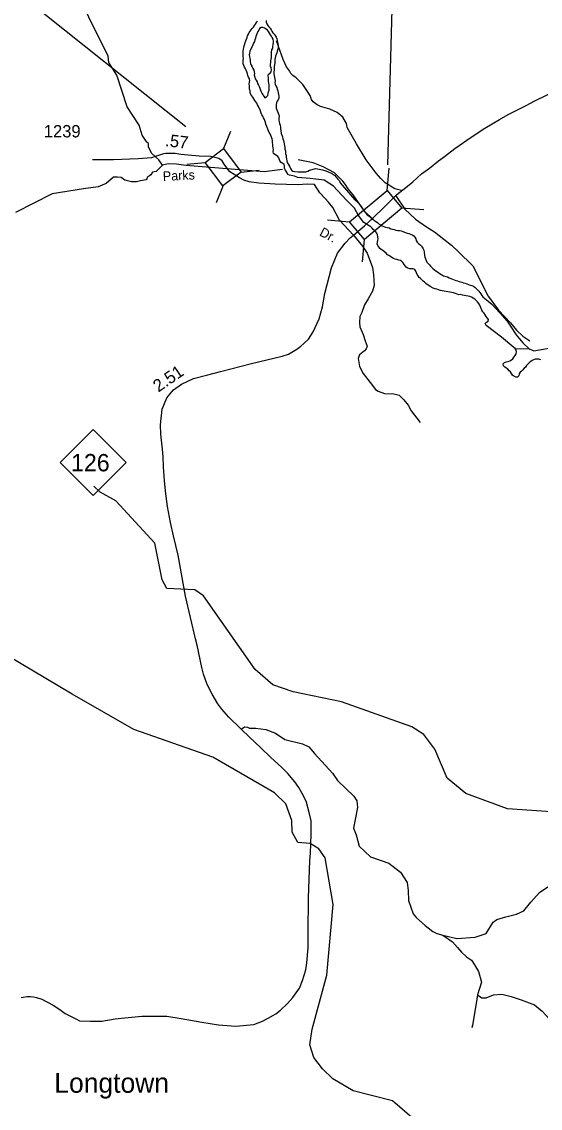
# Model space of a CAD drawing. Extents: x 1113032 to 1302912, y 664689 to 832535.
# Drawn here: x 1139525 to 1144769, y 747949 to 758928 of the extents above; entities that cross this region are included whole.
import ezdxf

# ---------------------------------------------------------------- set-up
doc = ezdxf.new("R2010")
doc.units = 0
for name, color, linetype in [('Exist Civil Demographics Community Label', 7, 'Continuous'), ('Exist Hydrographic Creek Single Shore', 7, 'Continuous'), ('Exist Hydrographic Island Shore', 7, 'Continuous'), ('Exist Hydrographic Lake Shore', 7, 'Continuous'), ('Exist Hydrographic River Shore', 7, 'Continuous'), ('Exist Road Non-System Type 51', 7, 'Continuous'), ('Exist Road Primary NC Attributed', 7, 'Continuous'), ('Exist Road Primary NC Service Mileage Hundredths English Label', 7, 'Continuous'), ('Exist Road Primary NC Shield CELL', 7, 'Continuous'), ('Exist Road Primary NC Shield Number Label', 7, 'Continuous'), ('Exist Road Primary NC Structure Standard Bridge CELL', 7, 'Continuous'), ('Exist Road Primary NC Structure Standard Bridge Number Label', 7, 'Continuous'), ('Exist Road Secondary Mileage Hundredths English Label', 7, 'Continuous'), ('Exist Road Secondary Structure Standard Bridge CELL', 7, 'Continuous'), ('Exist Road Secondary Structure Standard Bridge Number Label', 7, 'Continuous'), ('Exist Road Secondary Type 41 Attributed', 7, 'Continuous'), ('Exist Road Secondary Type 51 Label', 7, 'Continuous'), ('Exist Road Secondary Type 51 Number Label', 7, 'Continuous')]:
    doc.layers.add(name, color=color, linetype=linetype)

msp = doc.modelspace()

# ---------------------------------------------------------------- linework, layer by layer
at = {"layer": 'Exist Hydrographic Creek Single Shore'}
msp.add_line((1141976, 757410), (1141185, 757475), dxfattribs=at)
for points in [[(1140950, 757478), (1140911, 757533), (1140840, 757598), (1140808, 757662), (1140809, 757673), (1140809, 757696), (1140791, 757711), (1140745, 757780), (1140713, 757882), (1140593, 758068), (1140486, 758389), (1140406, 758515), (1140400, 758581), (1140007, 759370), (1139857, 759973), (1139719, 760111), (1139424, 760278)], [(1141185, 757475), (1141092, 757488), (1141006, 757491), (1140950, 757478), (1140886, 757415), (1140848, 757408), (1140830, 757381), (1140817, 757372), (1140795, 757358), (1140792, 757342), (1140785, 757332), (1140728, 757319), (1140687, 757309), (1140634, 757311), (1140568, 757327), (1140531, 757354), (1140493, 757356), (1140455, 757356), (1140380, 757293), (1140300, 757260), (1140150, 757240), (1139834, 757190), (1139461, 757001)], [(1144878, 750945), (1144436, 750974), (1144016, 751130), (1143828, 751284), (1143704, 751579), (1143591, 751726), (1143469, 751804), (1142759, 752057), (1142270, 752156), (1142063, 752229), (1141885, 752383), (1141364, 753126), (1141275, 753187), (1140992, 753202), (1140944, 753289), (1140872, 753658), (1140476, 754086), (1140320, 754174), (1140255, 754235)], [(1143517, 747815), (1143273, 748023), (1142876, 748126), (1142671, 748248), (1142566, 748346), (1142478, 748462), (1142439, 748591), (1142461, 748748), (1142610, 749293), (1142673, 750008), (1142595, 750479), (1142531, 750572), (1142441, 750626), (1142317, 750635), (1142261, 750738), (1142256, 750856), (1142195, 751025), (1142081, 751136), (1141458, 751496), (1140658, 751778), (1140034, 752132), (1139108, 752682)]]:
    msp.add_lwpolyline(points, dxfattribs=at)
at = {"layer": 'Exist Hydrographic Island Shore'}
msp.add_lwpolyline([(1141877, 758387), (1141882, 758369), (1141887, 758352), (1141895, 758336), (1141905, 758321), (1141910, 758303), (1141919, 758288), (1141927, 758272), (1141934, 758255), (1141939, 758238), (1141946, 758221), (1141955, 758205), (1141964, 758190), (1141974, 758175), (1141985, 758160), (1142002, 758170), (1142014, 758183), (1142019, 758202), (1142020, 758220), (1142027, 758237), (1142028, 758254), (1142029, 758272), (1142028, 758290), (1142024, 758308), (1142022, 758326), (1142022, 758344), (1142022, 758362), (1142018, 758380), (1142021, 758397), (1142037, 758408), (1142047, 758423), (1142050, 758443), (1142047, 758461), (1142041, 758478), (1142041, 758497), (1142043, 758515), (1142046, 758533), (1142049, 758551), (1142052, 758568), (1142052, 758586), (1142051, 758604), (1142051, 758622), (1142056, 758644), (1142064, 758661), (1142066, 758679), (1142069, 758697), (1142071, 758715), (1142071, 758733), (1142067, 758750), (1142059, 758767), (1142050, 758782), (1142040, 758797), (1142031, 758813), (1142021, 758828), (1142010, 758842), (1141996, 758853), (1141980, 758862), (1141964, 758868), (1141946, 758870), (1141931, 758859), (1141922, 758844), (1141914, 758828), (1141906, 758812), (1141898, 758795), (1141893, 758778), (1141889, 758761), (1141882, 758744), (1141878, 758727), (1141869, 758711), (1141862, 758694), (1141854, 758678), (1141847, 758662), (1141839, 758645), (1141833, 758629), (1141829, 758611), (1141825, 758593), (1141828, 758576), (1141831, 758558), (1141834, 758540), (1141837, 758522), (1141840, 758505), (1141846, 758488), (1141854, 758472), (1141863, 758456), (1141871, 758440), (1141876, 758423), (1141878, 758405), (1141877, 758387)], dxfattribs=at)
at = {"layer": 'Exist Hydrographic Lake Shore'}
msp.add_line((1144514, 755625), (1144655, 755623), dxfattribs=at)
for points in [[(1144591, 755684), (1144655, 755623), (1144705, 755601), (1144916, 755641), (1145275, 755897), (1145186, 755987), (1145139, 756067), (1145165, 756062), (1145181, 756050), (1145197, 756038)], [(1144774, 755513), (1144755, 755517), (1144736, 755518), (1144717, 755518), (1144687, 755505), (1144672, 755494), (1144657, 755482), (1144642, 755469), (1144630, 755454), (1144618, 755439), (1144605, 755426), (1144592, 755411), (1144578, 755398), (1144564, 755386), (1144554, 755369), (1144552, 755350), (1144540, 755336), (1144521, 755338), (1144503, 755346), (1144489, 755358), (1144477, 755373), (1144467, 755389), (1144454, 755402), (1144441, 755417), (1144427, 755429), (1144410, 755439), (1144396, 755452), (1144394, 755471), (1144406, 755485), (1144424, 755490), (1144443, 755495), (1144461, 755501), (1144478, 755510), (1144492, 755523), (1144503, 755539), (1144514, 755555), (1144525, 755572), (1144529, 755591), (1144525, 755609), (1144514, 755625), (1144502, 755635)]]:
    msp.add_lwpolyline(points, dxfattribs=at)
at = {"layer": 'Exist Hydrographic River Shore'}
for points in [[(1142284, 757367), (1142267, 757372), (1142249, 757374), (1142232, 757376), (1142216, 757385), (1142208, 757401), (1142200, 757417), (1142189, 757432), (1142184, 757449), (1142183, 757467), (1142178, 757484), (1142164, 757495), (1142148, 757505), (1142136, 757521), (1142126, 757551), (1142115, 757566), (1142100, 757575), (1142084, 757585), (1142071, 757597), (1142068, 757616), (1142070, 757634), (1142068, 757653), (1142066, 757671), (1142065, 757689), (1142062, 757707), (1142060, 757724), (1142057, 757743), (1142050, 757760), (1142044, 757777), (1142038, 757794), (1142029, 757809), (1142021, 757826), (1142014, 757843), (1142006, 757860), (1141999, 757876), (1141994, 757894), (1141989, 757911), (1141980, 757940), (1141971, 757956), (1141962, 757972), (1141954, 757988), (1141946, 758004), (1141941, 758023), (1141936, 758040), (1141926, 758055), (1141918, 758071), (1141911, 758088), (1141903, 758104), (1141892, 758119), (1141882, 758133), (1141872, 758149), (1141862, 758164), (1141851, 758178), (1141842, 758193), (1141837, 758210), (1141834, 758228), (1141830, 758245), (1141829, 758263), (1141827, 758281), (1141826, 758299), (1141830, 758317), (1141831, 758334), (1141827, 758352), (1141820, 758369), (1141813, 758386), (1141808, 758403), (1141802, 758420), (1141795, 758437), (1141788, 758453), (1141778, 758470), (1141772, 758487), (1141766, 758504), (1141764, 758522), (1141765, 758540), (1141767, 758558), (1141765, 758576), (1141764, 758594), (1141764, 758612), (1141765, 758630), (1141768, 758649), (1141772, 758667), (1141776, 758684), (1141780, 758702), (1141784, 758719), (1141791, 758736), (1141798, 758752), (1141805, 758769), (1141810, 758786), (1141817, 758803), (1141826, 758818), (1141845, 758846), (1141857, 758859), (1141868, 758874), (1141878, 758889), (1141889, 758902), (1141899, 758919), (1141908, 758934)], [(1141996, 758940), (1141997, 758922), (1142004, 758905), (1142014, 758890), (1142025, 758876), (1142037, 758862), (1142047, 758847), (1142055, 758831), (1142066, 758817), (1142078, 758803), (1142088, 758789), (1142097, 758773), (1142104, 758756)], [(1142104, 758756), (1142110, 758740), (1142113, 758722), (1142115, 758704), (1142117, 758686), (1142118, 758668), (1142116, 758650), (1142110, 758631), (1142105, 758614), (1142099, 758597), (1142091, 758580), (1142087, 758563), (1142085, 758545), (1142086, 758527), (1142084, 758509), (1142080, 758492), (1142079, 758474), (1142078, 758456), (1142077, 758438), (1142075, 758420), (1142074, 758402), (1142078, 758384), (1142081, 758367), (1142085, 758349), (1142087, 758331), (1142086, 758313), (1142089, 758295), (1142096, 758279), (1142104, 758262), (1142109, 758245), (1142115, 758228), (1142120, 758211), (1142123, 758193), (1142124, 758175), (1142124, 758157), (1142120, 758140), (1142110, 758125), (1142101, 758109), (1142097, 758091), (1142097, 758073), (1142099, 758055), (1142106, 758039), (1142113, 758022), (1142120, 758005), (1142126, 757988), (1142127, 757971), (1142125, 757953), (1142125, 757935), (1142128, 757917), (1142133, 757900), (1142138, 757882), (1142142, 757863), (1142143, 757845), (1142145, 757828), (1142148, 757797), (1142155, 757780), (1142163, 757765), (1142167, 757746), (1142171, 757729), (1142175, 757711), (1142178, 757693), (1142182, 757674), (1142185, 757657), (1142186, 757639), (1142193, 757622), (1142194, 757594), (1142198, 757576), (1142200, 757558), (1142203, 757541), (1142206, 757523), (1142211, 757506), (1142226, 757478), (1142235, 757462), (1142244, 757444), (1142254, 757429), (1142268, 757419), (1142286, 757414), (1142322, 757412), (1142344, 757410), (1142375, 757411), (1142398, 757412), (1142419, 757419), (1142435, 757428), (1142500, 757444), (1142551, 757435), (1142568, 757431), (1142599, 757422), (1142625, 757411), (1142649, 757401), (1142668, 757391), (1142687, 757376), (1142704, 757358), (1142723, 757337), (1142738, 757319), (1142747, 757300), (1142830, 757202), (1142890, 757131), (1142927, 757098), (1142947, 757076), (1142959, 757061)], [(1142162, 757434), (1141976, 757410)], [(1144245, 755920), (1144233, 755935), (1144222, 755951), (1144212, 755967), (1144201, 755983), (1144189, 755996), (1144178, 756012), (1144171, 756030), (1144164, 756048), (1144156, 756065), (1144146, 756082), (1144134, 756097), (1144121, 756110), (1144106, 756123), (1144091, 756134), (1144075, 756146), (1144057, 756151), (1144038, 756155), (1144020, 756159), (1144001, 756162), (1143982, 756165), (1143965, 756171), (1143946, 756170), (1143928, 756175), (1143910, 756183), (1143892, 756188), (1143873, 756191), (1143854, 756195), (1143835, 756199), (1143816, 756202), (1143797, 756204), (1143778, 756208), (1143759, 756212), (1143741, 756218), (1143723, 756224), (1143705, 756230), (1143687, 756237), (1143657, 756252), (1143641, 756262), (1143626, 756272), (1143612, 756283), (1143599, 756296), (1143586, 756308), (1143572, 756320), (1143559, 756333), (1143545, 756344), (1143534, 756359), (1143525, 756375), (1143517, 756391), (1143509, 756407), (1143500, 756423), (1143484, 756431), (1143466, 756431), (1143448, 756431), (1143429, 756438), (1143414, 756448), (1143401, 756461), (1143391, 756476), (1143382, 756492), (1143369, 756505), (1143354, 756515), (1143337, 756520), (1143319, 756524), (1143302, 756530), (1143284, 756535), (1143269, 756544), (1143254, 756555), (1143239, 756565), (1143223, 756574), (1143212, 756588), (1143198, 756600), (1143176, 756615), (1143161, 756625), (1143147, 756637), (1143137, 756652), (1143126, 756666), (1143121, 756683), (1143123, 756701), (1143126, 756719), (1143128, 756737), (1143126, 756756), (1143123, 756773), (1143117, 756791), (1143107, 756806), (1143093, 756817), (1143080, 756830), (1143068, 756843), (1143054, 756855), (1143038, 756864), (1142985, 756899), (1142931, 756971), (1142890, 757043), (1142805, 757128), (1142679, 757267), (1142585, 757326), (1142500, 757337), (1142442, 757345), (1142318, 757353), (1142301, 757360), (1142284, 757367)], [(1142959, 757061), (1142969, 757045), (1142977, 757029), (1142991, 757009), (1143004, 756994), (1143019, 756978), (1143035, 756967), (1143050, 756957), (1143096, 756917), (1143112, 756907), (1143126, 756896), (1143139, 756884), (1143155, 756875), (1143171, 756866), (1143188, 756859), (1143205, 756853), (1143223, 756849), (1143240, 756844), (1143257, 756836), (1143274, 756832), (1143292, 756827), (1143309, 756821), (1143327, 756819), (1143345, 756817), (1143363, 756815), (1143380, 756807), (1143406, 756797), (1143423, 756793), (1143441, 756788), (1143458, 756783), (1143475, 756776), (1143489, 756764), (1143500, 756750), (1143509, 756734), (1143515, 756717), (1143524, 756702), (1143537, 756688), (1143550, 756676), (1143563, 756664), (1143575, 756650), (1143585, 756634), (1143593, 756618), (1143596, 756600), (1143597, 756567), (1143601, 756550), (1143608, 756533), (1143616, 756516), (1143623, 756499), (1143636, 756486), (1143648, 756473), (1143659, 756459), (1143672, 756445), (1143684, 756433), (1143699, 756422), (1143714, 756411), (1143728, 756400), (1143743, 756390), (1143758, 756379), (1143773, 756369), (1143790, 756362), (1143813, 756354), (1143830, 756349), (1143847, 756341), (1143863, 756332), (1143880, 756327), (1143897, 756320), (1143914, 756314), (1143932, 756310), (1143949, 756303), (1143975, 756296), (1143993, 756291), (1144010, 756286), (1144027, 756281), (1144044, 756274), (1144060, 756267), (1144077, 756261), (1144094, 756255), (1144109, 756244), (1144122, 756232), (1144135, 756219), (1144146, 756206), (1144157, 756191), (1144168, 756177), (1144179, 756162), (1144188, 756147), (1144278, 756073), (1144359, 755987), (1144435, 755902), (1144467, 755853), (1144525, 755763), (1144591, 755684)], [(1144502, 755635), (1144376, 755742), (1144221, 755859), (1144212, 755880), (1144225, 755893), (1144242, 755902), (1144245, 755920)]]:
    msp.add_lwpolyline(points, dxfattribs=at)
at = {"layer": 'Exist Road Non-System Type 51'}
for points in [[(1143367, 757221), (1143298, 757240), (1143202, 757299), (1143157, 757344), (1143111, 757398), (1143009, 757533), (1142910, 757694), (1142816, 757860), (1142810, 757901), (1142771, 757964), (1142715, 758012), (1142642, 758046), (1142546, 758071), (1142513, 758088), (1142474, 758117), (1142454, 758143), (1142442, 758182), (1142367, 758292), (1142299, 758360), (1142266, 758383), (1142246, 758404), (1142233, 758432), (1142204, 758471), (1142168, 758546), (1142100, 758734)], [(1143070, 756940), (1142993, 757013), (1142878, 757180), (1142826, 757240), (1142797, 757287), (1142772, 757317), (1142689, 757402), (1142574, 757462), (1142471, 757501), (1142322, 757531)], [(1143307, 757168), (1143400, 757033), (1143507, 756932), (1143617, 756856), (1143698, 756806), (1143792, 756731), (1143872, 756671), (1143940, 756606), (1144086, 756460), (1144243, 756155), (1144347, 756012), (1144469, 755884), (1144529, 755812), (1144591, 755751), (1144664, 755702)], [(1142880, 756771), (1142971, 756661), (1143019, 756588), (1143071, 756444), (1143083, 756370), (1143089, 756263), (1143072, 756204), (1143027, 756129), (1142993, 756066), (1142965, 755989), (1142944, 755948), (1142940, 755888), (1142945, 755844), (1142977, 755768), (1142997, 755702), (1143017, 755651), (1143008, 755623), (1142992, 755604), (1142942, 755563), (1142926, 755524), (1142941, 755445), (1142979, 755372), (1143050, 755284), (1143102, 755212), (1143130, 755194), (1143195, 755170), (1143289, 755169), (1143343, 755155), (1143388, 755108), (1143432, 755053), (1143464, 754997), (1143553, 754877)], [(1141745, 751780), (1141779, 751803), (1141807, 751800), (1141828, 751789), (1141892, 751790), (1141995, 751776), (1142090, 751741), (1142185, 751674), (1142366, 751632), (1142429, 751600), (1142487, 751535), (1142667, 751334), (1142717, 751262), (1142803, 751181), (1142884, 751102), (1142915, 751054), (1142922, 750989), (1142896, 750867), (1142880, 750781), (1142908, 750712), (1142938, 750596), (1143051, 750489), (1143237, 750425), (1143355, 750334), (1143423, 750229), (1143433, 750151), (1143437, 750048), (1143482, 749914), (1143518, 749874), (1143605, 749795), (1143634, 749772), (1143683, 749737), (1143724, 749716), (1143784, 749699), (1143882, 749632), (1143933, 749573), (1143973, 749527), (1144023, 749481), (1144072, 749444), (1144104, 749400), (1144144, 749332), (1144176, 749225), (1144135, 749095), (1144128, 749051), (1144081, 748767), (1144082, 748787)], [(1143784, 749699), (1143924, 749663), (1144112, 749677), (1144222, 749714), (1144294, 749828), (1144328, 749858), (1144421, 749882), (1144527, 749910), (1144602, 749944), (1144674, 750033), (1144760, 750129), (1144866, 750201)], [(1144135, 749095), (1144179, 749065), (1144223, 749065), (1144297, 749097), (1144379, 749102), (1144474, 749077), (1144574, 749044), (1144711, 748993), (1144787, 748932), (1144862, 748851), (1144952, 748742)]]:
    msp.add_lwpolyline(points, dxfattribs=at)
at = {"layer": 'Exist Road Primary NC Attributed'}
for points in [[(1143055, 756926), (1143078, 756948), (1143192, 757057), (1143313, 757174), (1143319, 757182), (1143379, 757230), (1143427, 757266), (1143480, 757309), (1143569, 757391), (1143650, 757449), (1143738, 757521), (1143800, 757567), (1143906, 757647), (1144069, 757763), (1144209, 757853), (1144355, 757939), (1144443, 757990), (1144627, 758083), (1144714, 758127), (1144951, 758242)], [(1142880, 756771), (1142990, 756865), (1143055, 756926)], [(1142424, 750072), (1142437, 750453), (1142444, 750527), (1142453, 750716), (1142451, 750852), (1142433, 750938), (1142401, 751051), (1142362, 751130), (1142326, 751189), (1142286, 751246), (1142215, 751333), (1142152, 751395), (1142046, 751494), (1141940, 751595), (1141829, 751698), (1141741, 751784), (1141620, 751902), (1141550, 751982), (1141507, 752037), (1141450, 752132), (1141401, 752232), (1141365, 752337), (1141348, 752403), (1141298, 752629), (1141282, 752692), (1141183, 753125), (1141106, 753537), (1141059, 753732), (1141029, 753869), (1141000, 754029), (1140982, 754157), (1140970, 754289), (1140960, 754430), (1140957, 754531), (1140950, 754610), (1140931, 754759), (1140928, 754855), (1140946, 755013), (1140993, 755128), (1141060, 755209), (1141142, 755265), (1141264, 755324), (1141406, 755360), (1141534, 755395), (1141850, 755473), (1142160, 755550), (1142224, 755570), (1142308, 755620), (1142346, 755651), (1142378, 755678), (1142424, 755722), (1142473, 755796), (1142532, 755927), (1142566, 756048), (1142592, 756181), (1142657, 756441), (1142718, 756589), (1142797, 756690), (1142846, 756744), (1142880, 756771)], [(1139520, 749070), (1139580, 749079), (1139615, 749079), (1139645, 749076), (1139676, 749070), (1139730, 749052), (1139844, 748992), (1139910, 748948), (1139966, 748907), (1140073, 748853), (1140110, 748831), (1140221, 748829), (1140335, 748829), (1140470, 748854), (1140567, 748863), (1140739, 748880), (1140993, 748879), (1141137, 748857), (1141348, 748819), (1141515, 748792), (1141692, 748778), (1141874, 748796), (1141960, 748828), (1142019, 748860), (1142095, 748903), (1142143, 748941), (1142214, 749009), (1142266, 749070), (1142333, 749163), (1142364, 749239), (1142397, 749349), (1142410, 749420), (1142423, 749569), (1142421, 749722), (1142424, 750072)]]:
    msp.add_lwpolyline(points, dxfattribs=at)
at = {"layer": 'Exist Road Primary NC Shield CELL'}
msp.add_lwpolyline([(1139915, 754475), (1140248, 754808), (1140581, 754475), (1140248, 754142)], close=True, dxfattribs=at)
at = {"layer": 'Exist Road Primary NC Structure Standard Bridge CELL'}
for p, q in [((1143222, 757222), (1143242, 757448)), ((1143367, 757049), (1143593, 757029)), ((1142616, 756925), (1142841, 756905)), ((1142970, 756502), (1142990, 756727))]:
    msp.add_line(p, q, dxfattribs=at)
msp.add_lwpolyline([(1142841, 756905), (1143221, 757223), (1143370, 757045), (1142990, 756727)], close=True, dxfattribs=at)
at = {"layer": 'Exist Road Primary NC Structure Standard Bridge Number Label'}
msp.add_line((1143226, 757481), (1143323, 760794), dxfattribs=at)
at = {"layer": 'Exist Road Secondary Structure Standard Bridge CELL'}
for p, q in [((1141636, 757820), (1141566, 757647)), ((1141196, 757488), (1141381, 757507)), ((1141743, 757408), (1141928, 757428)), ((1141562, 757272), (1141492, 757099))]:
    msp.add_line(p, q, dxfattribs=at)
msp.add_lwpolyline([(1141566, 757647), (1141744, 757409), (1141559, 757269), (1141381, 757507)], close=True, dxfattribs=at)
at = {"layer": 'Exist Road Secondary Structure Standard Bridge Number Label'}
msp.add_line((1141184, 757866), (1138414, 760075), dxfattribs=at)
at = {"layer": 'Exist Road Secondary Type 41 Attributed'}
for points in [[(1141571, 757488), (1141552, 757522), (1141520, 757545), (1141436, 757565), (1141320, 757571), (1141136, 757588), (1141078, 757595), (1141048, 757597), (1141022, 757597), (1140982, 757597), (1140958, 757593), (1140909, 757577), (1140875, 757567), (1140839, 757552), (1140702, 757543), (1140454, 757531), (1140328, 757531), (1140240, 757533)], [(1142880, 756771), (1142737, 756924), (1142670, 757052), (1142628, 757104), (1142595, 757141), (1142540, 757198), (1142487, 757282), (1142412, 757285), (1142319, 757279), (1142087, 757285), (1141922, 757296), (1141826, 757309), (1141770, 757328), (1141727, 757349), (1141672, 757385), (1141630, 757412), (1141571, 757488)]]:
    msp.add_lwpolyline(points, dxfattribs=at)

# ---------------------------------------------------------------- texts
at = {"layer": 'Exist Civil Demographics Community Label'}
msp.add_text('Longtown', height=200, dxfattribs=at).set_placement((1139855, 748106))
at = {"layer": 'Exist Road Primary NC Service Mileage Hundredths English Label'}
msp.add_text('2.51', height=125, rotation=34.4174, dxfattribs=at).set_placement((1140907, 755180))
at = {"layer": 'Exist Road Primary NC Shield Number Label'}
msp.add_text('126', height=175, dxfattribs=at).set_placement((1140024, 754385))
at = {"layer": 'Exist Road Secondary Mileage Hundredths English Label'}
msp.add_text('.57', height=125, rotation=353.1449, dxfattribs=at).set_placement((1140972, 757671))
at = {"layer": 'Exist Road Secondary Type 51 Label'}
for s, rotation, p in [('Parks', 2.7216, (1140954, 757319)), ('Dr.', 331.8721, (1142528, 756772))]:
    msp.add_text(s, height=95, rotation=rotation, dxfattribs=at).set_placement(p)
at = {"layer": 'Exist Road Secondary Type 51 Number Label'}
msp.add_text('1239', height=125, dxfattribs=at).set_placement((1139749, 757759))

doc.saveas('drawing.dxf')
